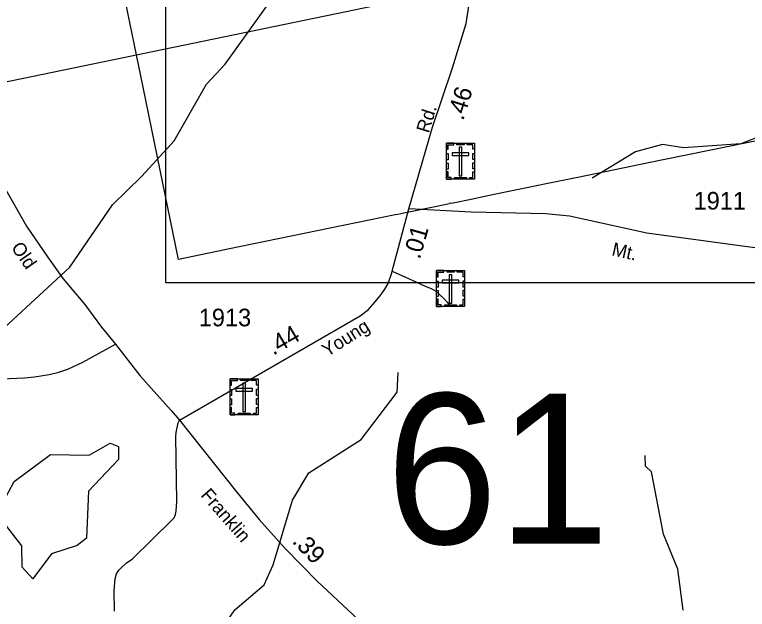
# Model space of a CAD drawing. Extents: x 2220236 to 2384410, y 720751 to 894131.
# Drawn here: x 2276098 to 2281300, y 800133 to 804354 of the extents above; entities that cross this region are included whole.
import ezdxf

# ---------------------------------------------------------------- set-up
doc = ezdxf.new("R2010")
doc.units = 0
for name, color, linetype in [('Exist Boundary Political City Limit New', 7, 'Continuous'), ('Exist Cultural Cemetery CELL', 7, 'Continuous'), ('Exist Hydrographic Misc Water Feature', 7, 'Continuous'), ('Exist Hydrographic Pond Under 1500 Sq Ft', 7, 'Continuous'), ('Exist Railroad Mainline', 7, 'Continuous'), ('Exist Road Non-System Type 51', 7, 'Continuous'), ('Exist Road Secondary Mileage Hundredths English Label', 7, 'Continuous'), ('Exist Road Secondary Structure Standard Bridge Number Label', 7, 'Continuous'), ('Exist Road Secondary Type 51 Attributed', 7, 'Continuous'), ('Exist Road Secondary Type 51 Label', 7, 'Continuous'), ('Exist Road Secondary Type 51 Number Label', 7, 'Continuous'), ('Map Preparation Boundary City Limit Buffer Line', 7, 'Continuous'), ('Map Preparation Inset Cut Line', 7, 'Continuous')]:
    doc.layers.add(name, color=color, linetype=linetype)

msp = doc.modelspace()

# ---------------------------------------------------------------- linework, layer by layer
at = {"layer": 'Exist Boundary Political City Limit New'}
msp.add_lwpolyline([(2281423.5, 803470.4), (2280899.8, 803363), (2280679, 803317.8), (2280096.5, 803198.4), (2279871.5, 803152.2), (2279733.5, 803123.9), (2279581.8, 803092.8), (2279457.2, 803067.3), (2279338.8, 803043), (2279222, 803019.1), (2279199.2, 803014.4), (2279186.2, 803014.8), (2279186, 803011.8), (2279083.5, 802990.8), (2278861, 802945.1), (2278817.5, 802936.2), (2278798.8, 802932.4), (2277691, 802705.3), (2277260.5, 802617.1), (2277111.8, 803343), (2277010.2, 803838.1), (2276949, 804136.2), (2276833, 804702.1)], dxfattribs=at)
at = {"layer": 'Exist Cultural Cemetery CELL'}
for points in [[(2279163.8, 803441.6), (2279362.9, 803441.6), (2279362.9, 803186.9), (2279163.8, 803186.9)], [(2279163.8, 803398.3), (2279175.2, 803398.3), (2279175.2, 803430.5), (2279215.7, 803430.4), (2279215.7, 803441.6), (2279163.8, 803441.6)], [(2279237.9, 803441.6), (2279289.7, 803441.6), (2279289.7, 803430.2), (2279237.9, 803430.2)], [(2279363, 803398.2), (2279351.6, 803398.2), (2279351.6, 803430.4), (2279311.1, 803430.4), (2279311.1, 803441.5), (2279363, 803441.5)], [(2279272.8, 803412.3), (2279254.2, 803412.3), (2279254.2, 803209.5), (2279272.8, 803209.5)], [(2279163.8, 803324.1), (2279163.8, 803367.4), (2279175.2, 803367.4), (2279175.2, 803324.1)], [(2279204.6, 803373.5), (2279204.6, 803354.8), (2279322.4, 803354.8), (2279322.4, 803373.5)], [(2279351.6, 803325.1), (2279351.6, 803368.5), (2279362.9, 803368.5), (2279362.9, 803325.1)], [(2279163.8, 803256.9), (2279163.8, 803300.2), (2279175.2, 803300.2), (2279175.2, 803256.9)], [(2279351.5, 803259.2), (2279351.5, 803302.5), (2279362.9, 803302.5), (2279362.9, 803259.2)], [(2279196.9, 803187), (2279196.9, 803198.5), (2279174.9, 803198.5), (2279174.9, 803238.9), (2279163.8, 803238.9), (2279163.8, 803187)], [(2279329.8, 803186.9), (2279329.8, 803198.4), (2279351.8, 803198.4), (2279351.8, 803238.8), (2279362.9, 803238.8), (2279362.9, 803186.9)], [(2279221.3, 803198.4), (2279306.1, 803198.4), (2279306.1, 803187), (2279221.3, 803187)], [(2279093.2, 802537.2), (2279292.3, 802537.2), (2279292.3, 802282.6), (2279093.2, 802282.6)], [(2279093.2, 802493.9), (2279104.6, 802493.9), (2279104.6, 802526.1), (2279145.1, 802526.1), (2279145.1, 802537.2), (2279093.2, 802537.2)], [(2279167.3, 802537.2), (2279219.1, 802537.2), (2279219.1, 802525.8), (2279167.3, 802525.8)], [(2279202.3, 802507.9), (2279183.6, 802507.9), (2279183.6, 802305.1), (2279202.3, 802305.1)], [(2279292.4, 802493.9), (2279281, 802493.9), (2279281, 802526.1), (2279240.5, 802526), (2279240.5, 802537.2), (2279292.4, 802537.2)], [(2279093.2, 802419.8), (2279093.2, 802463.1), (2279104.6, 802463.1), (2279104.6, 802419.8)], [(2279134, 802469.2), (2279134, 802450.5), (2279251.8, 802450.5), (2279251.8, 802469.2)], [(2279281, 802420.8), (2279281, 802464.1), (2279292.4, 802464.1), (2279292.4, 802420.8)], [(2279093.2, 802352.5), (2279093.2, 802395.9), (2279104.6, 802395.9), (2279104.6, 802352.5)], [(2279280.9, 802354.9), (2279280.9, 802398.2), (2279292.3, 802398.2), (2279292.3, 802354.9)], [(2279126.3, 802282.6), (2279126.3, 802294.1), (2279104.3, 802294.1), (2279104.3, 802334.5), (2279093.2, 802334.5), (2279093.2, 802282.6)], [(2279259.2, 802282.6), (2279259.2, 802294.1), (2279281.2, 802294.1), (2279281.2, 802334.5), (2279292.3, 802334.5), (2279292.3, 802282.6)], [(2279150.7, 802294.1), (2279235.5, 802294.1), (2279235.5, 802282.7), (2279150.7, 802282.7)], [(2277626.9, 801768.3), (2277826, 801768.3), (2277826, 801513.7), (2277626.9, 801513.7)], [(2277626.9, 801725), (2277638.3, 801725), (2277638.3, 801757.2), (2277678.8, 801757.2), (2277678.8, 801768.3), (2277626.9, 801768.3)], [(2277701, 801768.3), (2277752.8, 801768.3), (2277752.8, 801756.9), (2277701, 801756.9)], [(2277735.9, 801739), (2277717.3, 801739), (2277717.3, 801536.2), (2277735.9, 801536.2)], [(2277826.1, 801724.9), (2277814.7, 801724.9), (2277814.7, 801757.1), (2277774.2, 801757.1), (2277774.2, 801768.2), (2277826.1, 801768.2)], [(2277626.9, 801650.8), (2277626.9, 801694.1), (2277638.3, 801694.1), (2277638.3, 801650.8)], [(2277667.7, 801700.2), (2277667.7, 801681.5), (2277785.5, 801681.5), (2277785.5, 801700.2)], [(2277814.7, 801651.8), (2277814.7, 801695.2), (2277826.1, 801695.2), (2277826.1, 801651.8)], [(2277626.9, 801583.6), (2277626.9, 801626.9), (2277638.3, 801626.9), (2277638.3, 801583.6)], [(2277814.6, 801585.9), (2277814.6, 801629.2), (2277826, 801629.2), (2277826, 801585.9)], [(2277660, 801513.7), (2277660, 801525.2), (2277638, 801525.2), (2277638, 801565.6), (2277626.9, 801565.6), (2277626.9, 801513.7)], [(2277684.4, 801525.1), (2277769.2, 801525.1), (2277769.2, 801513.7), (2277684.4, 801513.7)], [(2277792.9, 801513.7), (2277792.9, 801525.1), (2277814.9, 801525.1), (2277814.9, 801565.6), (2277826, 801565.6), (2277826, 801513.7)]]:
    msp.add_lwpolyline(points, close=True, dxfattribs=at)
at = {"layer": 'Exist Hydrographic Misc Water Feature'}
for points in [[(2275569.1, 801225.9), (2275600, 801409), (2275732.1, 801652.3), (2275837.1, 801961.6), (2276489.1, 802561.5), (2276793, 803004.5), (2277000.1, 803206.9), (2277230, 803458), (2277460.1, 803860), (2277592.1, 804001.6), (2277904, 804437.9), (2277945, 804555.2), (2277942.1, 804840.5), (2277690.1, 805127.8), (2277472.2, 805276.6)], [(2281478.1, 803524.4), (2281254.2, 803437.2), (2280846.1, 803409.6), (2280696.2, 803432.3), (2280505.1, 803380.5), (2280198.1, 803193.4)], [(2275926, 796941.6), (2276305, 797311), (2276395, 797512.5), (2276576.1, 797754.7), (2276690.1, 798080.3), (2276862.1, 798391.7), (2276877.1, 798499.6), (2277065.1, 798892.5), (2277203.1, 799276.8), (2277294.2, 799392.9), (2277326.1, 799493.9), (2277466, 799638.6), (2277563, 799987.6), (2277662, 800129.8), (2277868.1, 800306), (2277933.1, 800449), (2278071.1, 800908.6), (2278186.1, 801103), (2278558.1, 801338), (2278813.2, 801673.9), (2278820.2, 801814.7)], [(2280843, 800126.4), (2280807.1, 800419), (2280705, 800667.2), (2280618.1, 801108.5), (2280576, 801148.8), (2280575, 801224.2)]]:
    msp.add_lwpolyline(points, dxfattribs=at)
at = {"layer": 'Exist Hydrographic Pond Under 1500 Sq Ft'}
msp.add_lwpolyline([(2276095, 801041.2), (2276352.2, 801232.7), (2276627.1, 801227), (2276776, 801312.5), (2276834, 801288.3), (2276835.1, 801196.5), (2276621, 800971.3), (2276607, 800637.1), (2276541, 800585.9), (2276359.1, 800527.4), (2276227.1, 800349.8), (2276151, 800433.3), (2276150, 800584.2), (2275998, 800780.9), (2276014, 800888.7), (2276095, 801041.2)], dxfattribs=at)
at = {"layer": 'Exist Railroad Mainline'}
msp.add_lwpolyline([(2273201.7, 803292.5), (2287925.2, 806334.9), (2293833.8, 807542.5)], dxfattribs=at)
at = {"layer": 'Exist Road Non-System Type 51'}
for points in [[(2278778.1, 802533.2), (2278873.3, 802490.5), (2278945, 802456.9), (2279012.2, 802427.7), (2279054.8, 802409.8), (2279087.3, 802390.3), (2279143.8, 802338.7), (2279167.9, 802313.1), (2279184.2, 802289.1)], [(2274435.5, 801337), (2274979, 801354.1), (2275011.1, 801356.5), (2275032.9, 801362.6), (2275052.7, 801370.8), (2275090.6, 801397.2), (2275397.5, 801719.8), (2275415.2, 801736), (2275437.1, 801750.2), (2275459, 801758.5), (2275478.8, 801762.7), (2275540.8, 801769.2), (2275946.6, 801767), (2276168.5, 801775), (2276238.2, 801783.8), (2276342.2, 801800.6), (2276411.9, 801817.4), (2276475.7, 801838.1), (2276581.3, 801886.9), (2276814.4, 802015.9)], [(2276807.2, 800119), (2276803.6, 800266.8), (2276810.8, 800349.8), (2276821.6, 800385.8), (2276836.9, 800410), (2276852.8, 800426.1), (2276890.1, 800461.6), (2276933.4, 800490.4), (2277217.3, 800767.4), (2277229.3, 800783.6), (2277239.1, 800805.6), (2277244.8, 800829.7), (2277248.2, 800897.6), (2277241.8, 801359.4), (2277243.5, 801387.3), (2277259, 801457.6), (2277268.8, 801475.6)]]:
    msp.add_lwpolyline(points, dxfattribs=at)
at = {"layer": 'Exist Road Secondary Type 51 Attributed'}
for points in [[(2274868, 805515.3), (2275230.3, 804631.3), (2275439.7, 804146), (2275637.3, 803794.2), (2275720.9, 803656.1), (2275814.4, 803497), (2275940.6, 803274.3), (2276023.8, 803131), (2276181.6, 802852.5), (2276331.6, 802634.4), (2276442, 802478.6), (2276596.3, 802295.9), (2276713.5, 802134.9), (2276814.4, 802015.9), (2276987.4, 801792.3), (2277210, 801545), (2277268.8, 801475.6)], [(2278895.7, 802974.9), (2279063.8, 803555.6), (2279206.1, 803976.1), (2279303.3, 804291.5), (2279329.6, 804461.7), (2279333.1, 804521.6), (2279332.9, 804555.5), (2279327.4, 804607.5)], [(2277268.8, 801475.6), (2278550.6, 802217), (2278608.9, 802261.8), (2278654.3, 802314.3), (2278691.8, 802358.5), (2278725.3, 802404.8), (2278748.9, 802445.1), (2278776.1, 802521.3), (2278778.1, 802533.2), (2278895.7, 802974.9)], [(2283646.8, 800324.9), (2283646, 800388.3), (2283642.1, 800449), (2283636.4, 800509.4), (2283622.9, 800594.6), (2283598.3, 800711.2), (2283566.9, 800839), (2283477.3, 801056.5), (2283404.5, 801185.5), (2283311.3, 801322.5), (2282780.8, 802035.2), (2282679.5, 802146.3), (2282509.2, 802301), (2282313.3, 802438.6), (2282196.7, 802507.4), (2282029.6, 802592.6), (2281827.7, 802634), (2281230.6, 802714.7), (2280586.7, 802802.2), (2280037.8, 802922.9), (2279868.3, 802941.2), (2279339.4, 802952.5), (2278895.7, 802974.9)], [(2277268.8, 801475.6), (2277673.3, 800966.8), (2277834.6, 800769.5), (2278018.9, 800565.1), (2278245.8, 800333.4), (2278497.9, 800096.8), (2278652.6, 799942.1)]]:
    msp.add_lwpolyline(points, dxfattribs=at)
at = {"layer": 'Map Preparation Boundary City Limit Buffer Line'}
msp.add_lwpolyline([(2281423.5, 803470.4), (2280899.8, 803363), (2280679, 803317.8), (2280096.5, 803198.4), (2279871.5, 803152.2), (2279733.5, 803123.9), (2279581.8, 803092.8), (2279457.2, 803067.3), (2279338.8, 803043), (2279222, 803019.1), (2279199.2, 803014.4), (2279186.2, 803014.8), (2279186, 803011.8), (2279083.5, 802990.8), (2278861, 802945.1), (2278817.5, 802936.2), (2278798.8, 802932.4), (2277691, 802705.3), (2277260.5, 802617.1), (2277111.8, 803343), (2277010.2, 803838.1), (2276949, 804136.2), (2276833, 804702.1)], dxfattribs=at)
at = {"layer": 'Map Preparation Inset Cut Line'}
msp.add_lwpolyline([(2277171, 809424), (2288659.7, 809424), (2288659.7, 802451.1), (2277171, 802451.1), (2277171, 809424)], dxfattribs=at)
msp.add_lwpolyline([(2277171, 809424), (2288659.7, 809424), (2288659.7, 802451.1), (2277171, 802451.1), (2277171, 809424)], dxfattribs=at)

# ---------------------------------------------------------------- texts
at = {"layer": 'Exist Road Secondary Mileage Hundredths English Label'}
for s, rotation, p in [('.46', 72.7085, (2279282.1, 803597.1)), ('.01', 73.874, (2278973.9, 802612.5)), ('.44', 30.0449, (2277933.9, 801932.4)), ('.39', 314.396, (2278062.2, 800610.2))]:
    msp.add_text(s, height=125, rotation=rotation, dxfattribs=at).set_placement(p)
at = {"layer": 'Exist Road Secondary Structure Standard Bridge Number Label'}
msp.add_text('61', height=1066.27, dxfattribs=at).set_placement((2278733.7, 800598.2))
at = {"layer": 'Exist Road Secondary Type 51 Label'}
for s, rotation, p in [('Rd.', 72.7085, (2279037.6, 803508.1)), ('Old', 304.8693, (2276069.5, 802700.3)), ('Mt.', 347.288, (2280331.7, 802646.7)), ('Young', 32.21, (2278316.9, 801921.8)), ('Franklin', 311.0418, (2277413.8, 800940.4))]:
    msp.add_text(s, height=95, rotation=rotation, dxfattribs=at).set_placement(p)
at = {"layer": 'Exist Road Secondary Type 51 Number Label'}
for s, p in [('1911', (2280917.9, 802970.6)), ('1913', (2277405.1, 802141.9))]:
    msp.add_text(s, height=125, dxfattribs=at).set_placement(p)

doc.saveas('drawing.dxf')
